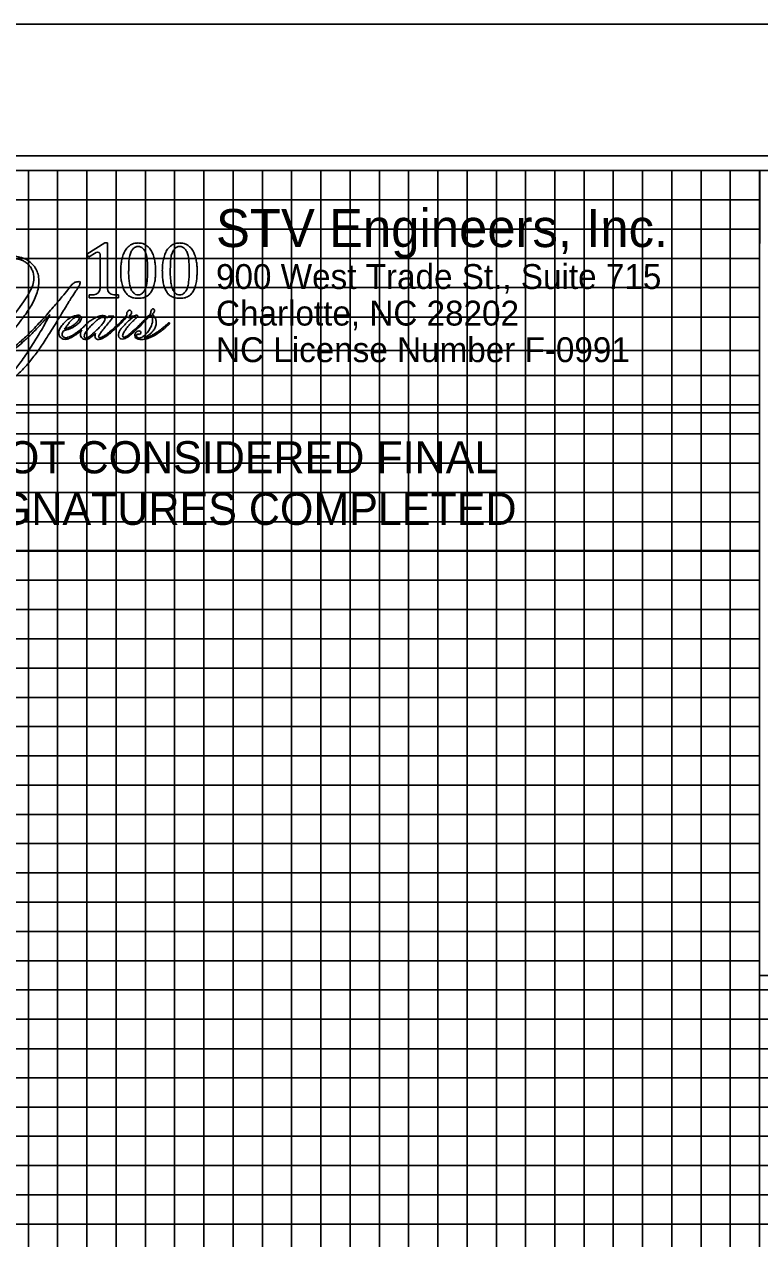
# Model space of a CAD drawing. Extents: x 1439200 to 3815465, y 598050 to 1224643.
# Drawn here: x 3815327.8 to 3815378.1, y 1224560.2 to 1224643.2 of the extents above; entities that cross this region are included whole.
import ezdxf

# ---------------------------------------------------------------- set-up
doc = ezdxf.new("R2010")
doc.units = 0
for name, color, linetype in [('COGO Default Curve', 7, 'Continuous'), ('Exist Roads EOP', 7, 'Continuous'), ('Pattern 49', 7, 'Continuous'), ('Profile Utility Text', 7, 'Continuous'), ('Scratch_Level_1', 7, 'Continuous'), ('Sheet Layout Plan Border', 7, 'Continuous'), ('UE Detail Plan Sheet w Clip 34 CELL', 7, 'Continuous')]:
    doc.layers.add(name, color=color, linetype=linetype)

msp = doc.modelspace()

# ---------------------------------------------------------------- linework, layer by layer
at = {"layer": 'COGO Default Curve'}
for p, q in [((3815298.107, 1224616.652), (3815378.107, 1224616.652)), ((3815378.107, 1224616.652), (3815378.107, 1224607.252)), ((3815378.107, 1224607.252), (3815298.107, 1224607.252))]:
    msp.add_line(p, q, dxfattribs=at)
at = {"layer": 'Exist Roads EOP'}
for p, q in [((3814878.107, 1224633.207), (3815378.107, 1224633.207)), ((3815378.107, 1224623.187), (3815378.132, 1224633.207)), ((3815438.107, 1224561.207), (3814878.107, 1224561.207))]:
    msp.add_line(p, q, dxfattribs=at)
for points in [[(3815458.107, 1224633.207), (3814858.107, 1224633.207), (3814858.107, 1224213.207), (3815458.107, 1224213.207)], [(3814878.107, 1224633.207), (3814878.107, 1224223.207), (3815438.107, 1224223.207), (3815438.107, 1224578.187), (3815378.107, 1224578.187), (3815378.107, 1224633.207)]]:
    msp.add_lwpolyline(points, close=True, dxfattribs=at)
for points in [[(3815328.107, 1224223.207), (3815328.107, 1224633.207), (3815348.107, 1224633.207), (3815348.107, 1224223.207)], [(3815330.107, 1224223.207), (3815330.107, 1224633.207), (3815332.107, 1224633.207), (3815332.107, 1224223.207)], [(3815334.107, 1224223.207), (3815334.107, 1224633.207), (3815336.107, 1224633.207), (3815336.107, 1224223.207)], [(3815338.107, 1224223.207), (3815338.107, 1224633.207), (3815358.107, 1224633.207), (3815358.107, 1224223.207)], [(3815340.107, 1224223.207), (3815340.107, 1224633.207), (3815342.107, 1224633.207), (3815342.107, 1224223.207)], [(3815344.107, 1224223.207), (3815344.107, 1224633.207), (3815346.107, 1224633.207), (3815346.107, 1224223.207)], [(3815350.107, 1224223.207), (3815350.107, 1224633.207), (3815352.107, 1224633.207), (3815352.107, 1224223.207)], [(3815354.107, 1224223.207), (3815354.107, 1224633.207), (3815356.107, 1224633.207), (3815356.107, 1224223.207)], [(3815360.107, 1224223.207), (3815360.107, 1224633.207), (3815362.107, 1224633.207), (3815362.107, 1224223.207)], [(3815364.107, 1224223.207), (3815364.107, 1224633.207), (3815366.107, 1224633.207), (3815366.107, 1224223.207)], [(3815368.107, 1224223.207), (3815368.107, 1224633.207)], [(3815370.107, 1224223.207), (3815370.107, 1224633.207), (3815372.107, 1224633.207), (3815372.107, 1224223.207)], [(3815374.107, 1224223.207), (3815374.107, 1224633.207), (3815376.107, 1224633.207), (3815376.107, 1224223.207)], [(3815378.107, 1224223.207), (3815378.107, 1224633.207), (3815388.627, 1224633.207)], [(3815418.137, 1224623.252), (3815418.137, 1224578.187), (3815378.107, 1224578.187), (3815378.107, 1224633.207), (3815418.137, 1224633.207), (3815418.137, 1224633.147)], [(3815378.087, 1224631.207), (3814878.107, 1224631.207), (3814878.107, 1224629.207), (3815378.087, 1224629.207)], [(3815378.087, 1224627.207), (3814878.107, 1224627.207), (3814878.107, 1224625.207), (3815378.087, 1224625.207)], [(3815378.087, 1224603.207), (3814858.147, 1224603.207), (3814858.147, 1224623.187), (3815378.087, 1224623.187)], [(3815378.087, 1224620.907), (3814878.107, 1224620.907), (3814878.107, 1224619.207), (3815378.087, 1224619.207)], [(3815378.087, 1224617.207), (3814878.107, 1224617.207), (3814878.107, 1224615.207), (3815378.087, 1224615.207)], [(3814858.107, 1224613.207), (3815378.087, 1224613.207)], [(3815378.087, 1224611.207), (3814878.107, 1224611.207), (3814878.107, 1224609.207), (3815378.087, 1224609.207)], [(3815378.107, 1224607.207), (3814878.107, 1224607.207), (3814878.107, 1224605.207), (3815378.087, 1224605.207)], [(3815378.087, 1224601.207), (3814878.107, 1224601.207), (3814878.107, 1224599.207), (3815378.087, 1224599.207)], [(3815378.087, 1224597.207), (3814878.107, 1224597.207), (3814878.107, 1224595.207), (3815378.087, 1224595.207)], [(3815378.087, 1224593.207), (3814858.107, 1224593.207), (3814858.107, 1224573.187), (3815458.107, 1224573.187)], [(3815378.087, 1224591.207), (3814878.107, 1224591.207), (3814878.107, 1224589.207), (3815378.087, 1224589.207)], [(3815378.087, 1224587.207), (3814878.107, 1224587.207), (3814878.107, 1224585.207), (3815378.087, 1224585.207)], [(3815458.107, 1224563.207), (3814858.107, 1224563.207), (3814858.107, 1224583.207), (3815378.087, 1224583.207)], [(3815378.087, 1224581.207), (3814878.107, 1224581.207), (3814878.107, 1224579.207), (3815378.087, 1224579.207)], [(3815438.107, 1224577.207), (3814878.107, 1224577.207), (3814878.107, 1224577.207), (3814878.107, 1224569.207), (3815438.107, 1224569.207)], [(3815438.107, 1224577.207), (3814878.107, 1224577.207), (3814878.107, 1224577.207), (3814878.107, 1224569.207), (3815458.107, 1224569.207)], [(3814878.107, 1224575.207), (3815438.107, 1224575.207)], [(3815438.107, 1224571.207), (3814878.107, 1224571.207)], [(3815438.107, 1224567.207), (3814878.107, 1224567.207), (3814878.107, 1224565.207), (3815438.107, 1224565.207)]]:
    msp.add_lwpolyline(points, dxfattribs=at)
at = {"layer": 'Pattern 49'}
msp.add_lwpolyline([(3815463.107, 1224634.227), (3814796.507, 1224634.227), (3814796.507, 1224212.187), (3815463.107, 1224212.187)], close=True, dxfattribs=at)
at = {"layer": 'Profile Utility Text'}
for points in [[(3815298.107, 1224633.207), (3815378.107, 1224633.207), (3815378.107, 1224607.252), (3815333.021, 1224607.252), (3815318.649, 1224607.252), (3815298.107, 1224607.252)], [(3815378.107, 1224578.187), (3815458.107, 1224578.187), (3815458.107, 1224569.207), (3815416.023, 1224569.207), (3815402.086, 1224569.207), (3815378.107, 1224569.207)]]:
    msp.add_lwpolyline(points, close=True, dxfattribs=at)
at = {"layer": 'Scratch_Level_1'}
msp.add_lwpolyline([(3815464.907, 1224643.207), (3814791.307, 1224643.207), (3814791.307, 1224203.207), (3815464.907, 1224203.207)], close=True, dxfattribs=at)
at = {"layer": 'Sheet Layout Plan Border'}
for p, q in [((3815333.337, 1224628.261), (3815332.095, 1224627.499)), ((3815333.51, 1224628.261), (3815333.337, 1224628.261)), ((3815333.51, 1224625.153), (3815333.51, 1224628.261)), ((3815332.095, 1224627.499), (3815332.222, 1224627.301)), ((3815332.222, 1224627.301), (3815332.737, 1224627.617)), ((3815333.008, 1224627.465), (3815333.008, 1224625.153)), ((3815332.581, 1224624.726), (3815332.261, 1224624.726)), ((3815332.261, 1224624.726), (3815332.261, 1224624.517)), ((3815332.261, 1224624.517), (3815334.258, 1224624.517)), ((3815334.258, 1224624.726), (3815333.938, 1224624.726)), ((3815334.258, 1224624.517), (3815334.258, 1224624.726)), ((3815335.613, 1224624.718), (3815335.61, 1224624.718)), ((3815335.611, 1224624.489), (3815335.612, 1224624.489)), ((3815338.456, 1224624.718), (3815338.454, 1224624.718)), ((3815338.455, 1224624.489), (3815338.455, 1224624.489))]:
    msp.add_line(p, q, dxfattribs=at)
msp.add_lwpolyline([(3815298.107, 1224633.207), (3815378.107, 1224633.207), (3815378.107, 1224616.652), (3815298.107, 1224616.652)], close=True, dxfattribs=at)
for centre, radius, start, end in [((3815332.83, 1224627.465), 0.178, 360, 121.52681), ((3815332.581, 1224625.153), 0.428, 270, 0), ((3815333.938, 1224625.153), 0.428, 180, 270)]:
    msp.add_arc(centre, radius, start, end, dxfattribs=at)
for points, degree in [([(3815335.611, 1224628.261), (3815335.58, 1224628.26), (3815335.478, 1224628.257), (3815335.31, 1224628.228), (3815335.097, 1224628.14), (3815334.88, 1224627.971), (3815334.681, 1224627.703), (3815334.561, 1224627.388), (3815334.47, 1224627.04), (3815334.43, 1224626.713), (3815334.423, 1224626.482), (3815334.421, 1224626.389)], 3), ([(3815334.964, 1224626.389), (3815334.968, 1224626.538), (3815334.977, 1224626.832), (3815334.991, 1224627.239), (3815335.078, 1224627.566), (3815335.193, 1224627.785), (3815335.31, 1224627.917), (3815335.425, 1224627.992), (3815335.513, 1224628.02), (3815335.575, 1224628.024), (3815335.611, 1224628.027)], 3), ([(3815336.802, 1224626.389), (3815336.799, 1224626.482), (3815336.793, 1224626.713), (3815336.753, 1224627.04), (3815336.662, 1224627.388), (3815336.541, 1224627.703), (3815336.342, 1224627.971), (3815336.126, 1224628.14), (3815335.913, 1224628.228), (3815335.745, 1224628.257), (3815335.643, 1224628.26), (3815335.611, 1224628.261)], 3), ([(3815335.611, 1224628.027), (3815335.648, 1224628.024), (3815335.71, 1224628.02), (3815335.798, 1224627.992), (3815335.913, 1224627.917), (3815336.03, 1224627.785), (3815336.145, 1224627.566), (3815336.232, 1224627.239), (3815336.246, 1224626.832), (3815336.254, 1224626.538), (3815336.259, 1224626.389)], 3), ([(3815338.455, 1224628.261), (3815338.424, 1224628.26), (3815338.321, 1224628.257), (3815338.154, 1224628.228), (3815337.94, 1224628.14), (3815337.724, 1224627.971), (3815337.525, 1224627.703), (3815337.405, 1224627.388), (3815337.314, 1224627.04), (3815337.274, 1224626.713), (3815337.267, 1224626.482), (3815337.265, 1224626.389)], 3), ([(3815337.808, 1224626.389), (3815337.812, 1224626.538), (3815337.821, 1224626.832), (3815337.835, 1224627.239), (3815337.922, 1224627.566), (3815338.036, 1224627.785), (3815338.153, 1224627.917), (3815338.269, 1224627.992), (3815338.357, 1224628.02), (3815338.419, 1224628.024), (3815338.455, 1224628.027)], 3), ([(3815339.646, 1224626.389), (3815339.643, 1224626.482), (3815339.636, 1224626.713), (3815339.597, 1224627.04), (3815339.505, 1224627.388), (3815339.385, 1224627.703), (3815339.186, 1224627.971), (3815338.97, 1224628.14), (3815338.756, 1224628.228), (3815338.589, 1224628.257), (3815338.486, 1224628.26), (3815338.455, 1224628.261)], 3), ([(3815338.455, 1224628.027), (3815338.491, 1224628.024), (3815338.553, 1224628.02), (3815338.641, 1224627.992), (3815338.757, 1224627.917), (3815338.874, 1224627.785), (3815338.989, 1224627.566), (3815339.075, 1224627.239), (3815339.09, 1224626.832), (3815339.098, 1224626.538), (3815339.102, 1224626.389)], 3), ([(3815329.579, 1224623.37), (3815329.48, 1224623.182), (3815329.145, 1224622.541), (3815328.559, 1224621.583), (3815327.905, 1224620.564), (3815327.301, 1224619.72), (3815326.755, 1224619.129), (3815326.278, 1224618.692), (3815325.912, 1224618.471), (3815325.578, 1224618.312), (3815325.273, 1224618.284), (3815325.005, 1224618.326), (3815324.819, 1224618.475), (3815324.729, 1224618.652), (3815324.739, 1224618.8), (3815324.823, 1224618.892), (3815324.952, 1224618.897), (3815325.113, 1224618.904), (3815325.316, 1224618.974), (3815325.376, 1224619.217), (3815325.208, 1224619.41), (3815324.944, 1224619.393), (3815324.741, 1224619.217), (3815324.57, 1224618.983), (3815324.588, 1224618.694), (3815324.672, 1224618.439), (3815324.863, 1224618.251), (3815325.148, 1224618.157), (3815325.447, 1224618.169), (3815325.782, 1224618.232), (3815326.176, 1224618.393), (3815326.609, 1224618.663), (3815327.118, 1224619.03), (3815327.702, 1224619.583), (3815328.276, 1224620.224), (3815328.842, 1224620.996), (3815329.371, 1224621.797), (3815330.015, 1224622.822), (3815330.587, 1224623.772), (3815331.072, 1224624.563), (3815331.375, 1224625.002), (3815331.546, 1224625.309), (3815331.648, 1224625.457), (3815331.669, 1224625.635), (3815331.494, 1224625.613), (3815331.348, 1224625.603), (3815331.179, 1224625.505), (3815330.995, 1224625.331), (3815330.752, 1224624.985), (3815330.309, 1224624.456), (3815329.642, 1224623.687), (3815328.836, 1224622.757), (3815327.977, 1224621.898), (3815327.33, 1224621.296), (3815326.897, 1224621.026), (3815326.704, 1224620.914), (3815326.492, 1224620.904), (3815326.428, 1224621.1), (3815326.477, 1224621.314), (3815326.661, 1224621.749), (3815326.984, 1224622.165), (3815327.421, 1224622.729), (3815327.888, 1224623.348), (3815328.443, 1224624.171), (3815328.82, 1224625.107), (3815328.854, 1224626.058), (3815328.487, 1224626.765), (3815327.968, 1224627.164), (3815327.513, 1224627.304), (3815327.23, 1224627.348), (3815327.124, 1224627.359)], 3), ([(3815327.277, 1224627.183), (3815327.281, 1224627.182), (3815327.347, 1224627.169), (3815327.47, 1224627.146), (3815327.702, 1224627.074), (3815327.938, 1224626.939), (3815328.175, 1224626.739), (3815328.324, 1224626.502), (3815328.443, 1224626.242), (3815328.481, 1224625.926), (3815328.461, 1224625.507), (3815328.279, 1224625.035), (3815327.959, 1224624.515), (3815327.58, 1224623.964), (3815327.008, 1224623.21), (3815326.426, 1224622.443), (3815326.116, 1224621.654), (3815326.097, 1224621.181), (3815326.2, 1224620.905), (3815326.385, 1224620.765), (3815326.559, 1224620.758), (3815326.796, 1224620.797), (3815327.062, 1224620.953), (3815327.382, 1224621.175), (3815327.809, 1224621.568), (3815328.345, 1224622.056), (3815328.964, 1224622.718), (3815329.362, 1224623.14), (3815329.579, 1224623.37)], 3), ([(3815334.421, 1224626.389), (3815334.423, 1224626.313), (3815334.43, 1224626.114), (3815334.434, 1224625.794), (3815334.504, 1224625.445), (3815334.6, 1224625.113), (3815334.756, 1224624.846), (3815334.947, 1224624.65), (3815335.225, 1224624.499), (3815335.458, 1224624.493), (3815335.611, 1224624.489)], 3), ([(3815335.61, 1224624.718), (3815335.559, 1224624.722), (3815335.437, 1224624.732), (3815335.272, 1224624.854), (3815335.128, 1224625.072), (3815335.027, 1224625.369), (3815334.993, 1224625.723), (3815334.958, 1224626.064), (3815334.962, 1224626.287), (3815334.964, 1224626.389)], 3), ([(3815335.612, 1224624.489), (3815335.765, 1224624.493), (3815335.998, 1224624.499), (3815336.276, 1224624.65), (3815336.467, 1224624.846), (3815336.622, 1224625.113), (3815336.718, 1224625.445), (3815336.789, 1224625.794), (3815336.793, 1224626.114), (3815336.799, 1224626.313), (3815336.802, 1224626.389)], 3), ([(3815336.259, 1224626.389), (3815336.261, 1224626.287), (3815336.265, 1224626.064), (3815336.23, 1224625.723), (3815336.196, 1224625.369), (3815336.094, 1224625.072), (3815335.951, 1224624.854), (3815335.786, 1224624.732), (3815335.664, 1224624.722), (3815335.613, 1224624.718)], 3), ([(3815337.265, 1224626.389), (3815337.267, 1224626.313), (3815337.274, 1224626.114), (3815337.277, 1224625.794), (3815337.348, 1224625.445), (3815337.444, 1224625.113), (3815337.6, 1224624.846), (3815337.791, 1224624.65), (3815338.069, 1224624.499), (3815338.301, 1224624.493), (3815338.455, 1224624.489)], 3), ([(3815338.454, 1224624.718), (3815338.403, 1224624.722), (3815338.281, 1224624.732), (3815338.115, 1224624.854), (3815337.972, 1224625.072), (3815337.87, 1224625.369), (3815337.837, 1224625.723), (3815337.802, 1224626.064), (3815337.806, 1224626.287), (3815337.808, 1224626.389)], 3), ([(3815338.455, 1224624.489), (3815338.609, 1224624.493), (3815338.842, 1224624.499), (3815339.119, 1224624.65), (3815339.31, 1224624.846), (3815339.466, 1224625.113), (3815339.562, 1224625.445), (3815339.633, 1224625.794), (3815339.636, 1224626.114), (3815339.643, 1224626.313), (3815339.646, 1224626.389)], 3), ([(3815339.102, 1224626.389), (3815339.104, 1224626.287), (3815339.108, 1224626.064), (3815339.074, 1224625.723), (3815339.04, 1224625.369), (3815338.938, 1224625.072), (3815338.795, 1224624.854), (3815338.629, 1224624.732), (3815338.508, 1224624.722), (3815338.456, 1224624.718)], 3), ([(3815336.019, 1224621.775), (3815336.06, 1224621.797), (3815336.194, 1224621.867), (3815336.403, 1224622.012), (3815336.61, 1224622.199), (3815336.765, 1224622.425), (3815336.845, 1224622.676), (3815336.854, 1224622.946), (3815336.771, 1224623.146), (3815336.671, 1224623.263), (3815336.635, 1224623.342), (3815336.592, 1224623.387), (3815336.608, 1224623.448), (3815336.675, 1224623.472), (3815336.718, 1224623.556), (3815336.742, 1224623.646), (3815336.707, 1224623.76), (3815336.587, 1224623.77), (3815336.516, 1224623.686), (3815336.464, 1224623.581), (3815336.491, 1224623.428), (3815336.326, 1224623.304), (3815336.156, 1224623.103), (3815335.85, 1224622.807), (3815335.545, 1224622.496), (3815335.265, 1224622.259), (3815335.104, 1224622.103), (3815334.969, 1224621.986), (3815334.827, 1224621.894), (3815334.717, 1224621.823), (3815334.576, 1224621.801), (3815334.538, 1224621.936), (3815334.57, 1224622.041), (3815334.653, 1224622.193), (3815334.776, 1224622.379), (3815334.944, 1224622.599), (3815335.114, 1224622.78), (3815335.287, 1224622.949), (3815335.431, 1224623.106), (3815335.557, 1224623.191), (3815335.612, 1224623.271), (3815335.543, 1224623.356), (3815335.429, 1224623.3), (3815335.306, 1224623.256), (3815335.194, 1224623.267), (3815334.981, 1224623.267), (3815335.043, 1224623.326), (3815335.081, 1224623.367), (3815335.168, 1224623.438), (3815335.167, 1224623.582), (3815335.069, 1224623.677), (3815334.948, 1224623.654), (3815334.869, 1224623.563), (3815334.822, 1224623.454), (3815334.84, 1224623.365), (3815334.79, 1224623.235), (3815334.627, 1224623.094), (3815334.384, 1224622.842), (3815334.095, 1224622.556), (3815333.733, 1224622.245), (3815333.432, 1224622), (3815333.187, 1224621.848), (3815333.062, 1224621.782), (3815332.967, 1224621.774), (3815332.91, 1224621.814), (3815332.906, 1224621.884), (3815332.941, 1224621.953), (3815333.026, 1224622.096), (3815333.175, 1224622.304), (3815333.454, 1224622.631), (3815333.715, 1224622.953), (3815333.894, 1224623.192), (3815333.949, 1224623.266)], 3), ([(3815333.471, 1224623.121), (3815333.462, 1224623.211), (3815333.416, 1224623.286), (3815333.222, 1224623.302), (3815332.959, 1224623.285), (3815332.68, 1224623.157), (3815332.445, 1224623.018), (3815332.199, 1224622.849), (3815331.979, 1224622.631), (3815331.756, 1224622.4), (3815331.433, 1224622.156), (3815331.315, 1224622.078), (3815331.115, 1224621.94), (3815330.901, 1224621.853), (3815330.721, 1224621.773), (3815330.575, 1224621.785), (3815330.472, 1224621.839), (3815330.405, 1224621.944), (3815330.406, 1224622.082), (3815330.469, 1224622.178), (3815330.511, 1224622.273), (3815330.641, 1224622.29), (3815330.819, 1224622.35), (3815331.038, 1224622.423), (3815331.266, 1224622.564), (3815331.503, 1224622.714), (3815331.684, 1224622.926), (3815331.765, 1224623.171), (3815331.633, 1224623.326), (3815331.478, 1224623.322), (3815331.273, 1224623.305), (3815331.014, 1224623.178), (3815330.707, 1224622.985), (3815330.449, 1224622.69), (3815330.232, 1224622.425), (3815330.179, 1224622.159), (3815330.193, 1224621.979), (3815330.269, 1224621.815), (3815330.4, 1224621.722), (3815330.552, 1224621.666), (3815330.735, 1224621.672), (3815330.989, 1224621.761), (3815331.254, 1224621.924), (3815331.535, 1224622.108), (3815331.685, 1224622.249), (3815331.757, 1224622.317)], 3), ([(3815330.585, 1224622.374), (3815330.635, 1224622.45), (3815330.728, 1224622.589), (3815330.903, 1224622.828), (3815331.081, 1224623.025), (3815331.277, 1224623.157), (3815331.387, 1224623.234), (3815331.488, 1224623.253), (3815331.561, 1224623.229), (3815331.607, 1224623.146), (3815331.553, 1224623.011), (3815331.452, 1224622.87), (3815331.293, 1224622.715), (3815331.099, 1224622.577), (3815330.905, 1224622.498), (3815330.734, 1224622.423), (3815330.642, 1224622.393), (3815330.585, 1224622.374)], 3), ([(3815332.66, 1224622.188), (3815332.586, 1224622.125), (3815332.415, 1224621.98), (3815332.216, 1224621.801), (3815332.024, 1224621.747), (3815331.916, 1224621.799), (3815331.92, 1224621.947), (3815332.013, 1224622.158), (3815332.279, 1224622.491), (3815332.578, 1224622.804), (3815332.849, 1224623.04), (3815333.009, 1224623.139), (3815333.144, 1224623.182), (3815333.269, 1224623.196), (3815333.406, 1224623.068), (3815333.238, 1224622.821), (3815333.052, 1224622.594), (3815332.842, 1224622.367), (3815332.708, 1224622.235), (3815332.66, 1224622.188)], 3), ([(3815332.691, 1224622.087), (3815332.681, 1224622.051), (3815332.657, 1224621.964), (3815332.645, 1224621.822), (3815332.737, 1224621.675), (3815332.915, 1224621.667), (3815333.167, 1224621.7), (3815333.461, 1224621.922), (3815333.803, 1224622.16), (3815334.074, 1224622.427), (3815334.324, 1224622.658), (3815334.571, 1224622.916), (3815334.749, 1224623.108), (3815334.848, 1224623.215)], 3), ([(3815333.594, 1224623.266), (3815333.553, 1224623.217), (3815333.512, 1224623.169), (3815333.471, 1224623.121)], 2), ([(3815333.949, 1224623.266), (3815333.831, 1224623.266), (3815333.712, 1224623.266), (3815333.594, 1224623.266)], 2), ([(3815335.217, 1224623.141), (3815335.128, 1224623.075), (3815334.947, 1224622.94), (3815334.738, 1224622.72), (3815334.549, 1224622.526), (3815334.41, 1224622.365), (3815334.314, 1224622.196), (3815334.258, 1224622.024), (3815334.258, 1224621.823), (3815334.43, 1224621.678), (3815334.638, 1224621.699), (3815334.843, 1224621.78), (3815335.074, 1224621.963), (3815335.378, 1224622.208), (3815335.855, 1224622.693), (3815336.23, 1224623.074), (3815336.49, 1224623.339)], 3), ([(3815334.848, 1224623.215), (3815334.883, 1224623.195), (3815334.96, 1224623.15), (3815335.091, 1224623.139), (3815335.179, 1224623.14), (3815335.217, 1224623.141)], 3), ([(3815336.49, 1224623.339), (3815336.515, 1224623.313), (3815336.589, 1224623.236), (3815336.602, 1224623.025), (3815336.595, 1224622.777), (3815336.466, 1224622.486), (3815336.298, 1224622.192), (3815336.08, 1224621.959), (3815335.894, 1224621.821), (3815335.741, 1224621.76), (3815335.605, 1224621.765), (3815335.519, 1224621.825), (3815335.476, 1224621.9), (3815335.505, 1224621.977), (3815335.561, 1224622.028), (3815335.635, 1224622.021), (3815335.719, 1224622.007), (3815335.793, 1224622.075), (3815335.826, 1224622.172), (3815335.723, 1224622.253), (3815335.579, 1224622.262), (3815335.451, 1224622.156), (3815335.384, 1224622.019), (3815335.374, 1224621.852), (3815335.498, 1224621.708), (3815335.74, 1224621.666), (3815336.033, 1224621.658), (3815336.353, 1224621.762), (3815336.686, 1224621.906), (3815337.005, 1224622.121), (3815337.357, 1224622.367), (3815337.59, 1224622.59), (3815337.754, 1224622.721), (3815337.766, 1224622.817), (3815337.689, 1224622.807), (3815337.602, 1224622.72), (3815337.461, 1224622.582), (3815337.211, 1224622.385), (3815336.951, 1224622.182), (3815336.663, 1224622.006), (3815336.412, 1224621.881), (3815336.201, 1224621.776), (3815336.067, 1224621.775), (3815336.019, 1224621.775)], 3), ([(3815331.757, 1224622.317), (3815331.731, 1224622.268), (3815331.687, 1224622.181), (3815331.656, 1224622.025), (3815331.678, 1224621.855), (3815331.8, 1224621.719), (3815331.968, 1224621.659), (3815332.141, 1224621.672), (3815332.308, 1224621.762), (3815332.446, 1224621.868), (3815332.574, 1224621.983), (3815332.651, 1224622.052), (3815332.691, 1224622.087)], 3)]:
    msp.add_open_spline(points, degree=degree, dxfattribs=at)
at = {"layer": 'UE Detail Plan Sheet w Clip 34 CELL'}
msp.add_lwpolyline([(3815378.107, 1224578.187), (3815458.107, 1224578.187), (3815458.107, 1224569.207), (3815378.107, 1224569.207)], close=True, dxfattribs=at)

# ---------------------------------------------------------------- texts
at = {"layer": 'COGO Default Curve'}
for s, p in [('DOCUMENT NOT CONSIDERED FINAL', (3815306.627, 1224612.514)), ('UNLESS ALL SIGNATURES COMPLETED', (3815304.599, 1224608.994))]:
    msp.add_text(s, height=2.2, rotation=360, dxfattribs=at).set_placement(p)
at = {"layer": 'Sheet Layout Plan Border'}
for s, height, p in [('STV Engineers, Inc.', 2.6, (3815340.936, 1224627.982)), ('900 West Trade St., Suite 715', 1.7, (3815340.936, 1224625.116)), ('Charlotte, NC 28202', 1.7, (3815340.936, 1224622.616)), ('NC License Number F-0991', 1.7, (3815340.936, 1224620.116))]:
    msp.add_text(s, height=height, rotation=360, dxfattribs=at).set_placement(p)

doc.saveas('drawing.dxf')
